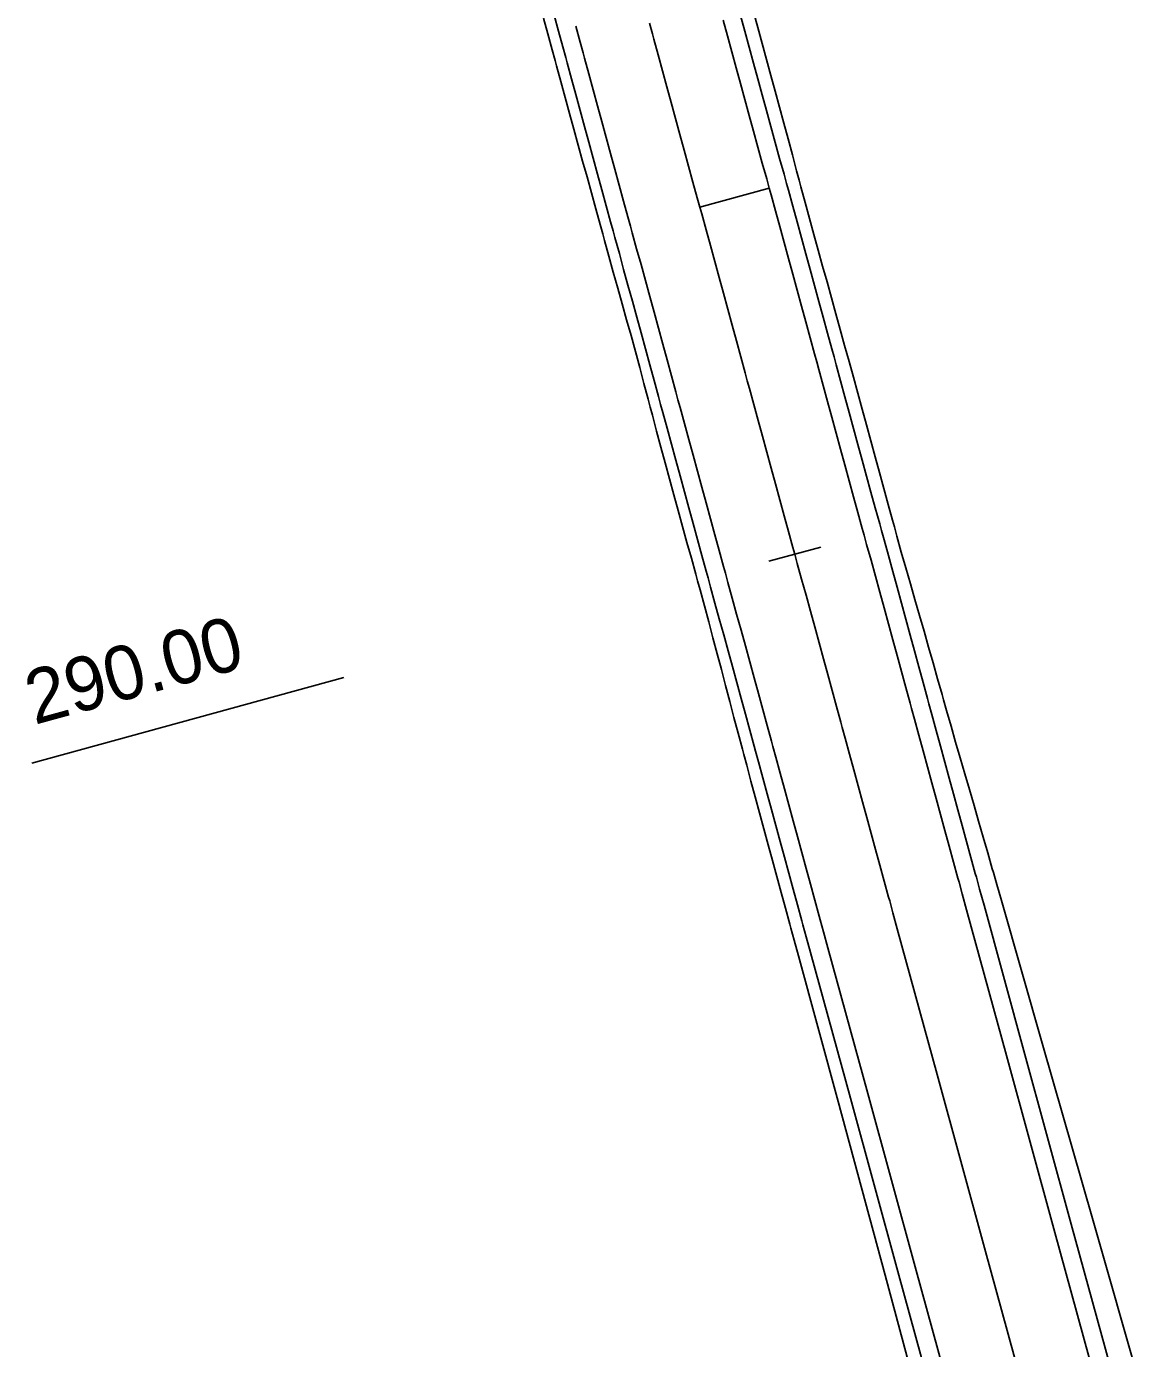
# Model space of a CAD drawing. Extents: x -550605 to -538780, y -1102367 to -1093705.
# Drawn here: x -547399.79 to -547368.77, y -1100986.96 to -1100950.2 of the extents above; entities that cross this region are included whole.
import ezdxf

# ---------------------------------------------------------------- set-up
doc = ezdxf.new("R2010")
doc.units = 0
for name, color, linetype in [('SIT - hrany vozovky', 7, 'Continuous'), ('SIT - osa cesty', 7, 'Continuous'), ('SIT - paty násypů', 7, 'Continuous'), ('SIT - staničení po 100m', 7, 'Continuous'), ('SIT - staničení po 30m', 7, 'Continuous')]:
    doc.layers.add(name, color=color, linetype=linetype)

msp = doc.modelspace()

# ---------------------------------------------------------------- linework, layer by layer
at = {"layer": 'SIT - hrany vozovky'}
for points in [[(-547374.237, -1100989.621), (-547375.55, -1100984.825), (-547376.87, -1100980.003), (-547377.978, -1100975.954), (-547378.099, -1100975.512), (-547378.19, -1100975.18), (-547378.22, -1100975.071), (-547378.341, -1100974.629), (-547378.462, -1100974.187), (-547378.583, -1100973.745), (-547378.703, -1100973.303), (-547378.824, -1100972.862), (-547378.945, -1100972.42), (-547379.066, -1100971.978), (-547379.187, -1100971.536), (-547379.308, -1100971.095), (-547379.429, -1100970.653), (-547379.51, -1100970.357), (-547379.55, -1100970.211), (-547379.671, -1100969.769), (-547379.792, -1100969.327), (-547379.913, -1100968.886), (-547380.034, -1100968.444), (-547380.155, -1100968.002), (-547380.275, -1100967.56), (-547380.396, -1100967.118), (-547380.517, -1100966.677), (-547380.638, -1100966.235), (-547380.759, -1100965.793), (-547380.83, -1100965.535), (-547380.88, -1100965.351), (-547381.001, -1100964.909), (-547381.122, -1100964.468), (-547381.243, -1100964.026), (-547381.364, -1100963.584), (-547381.485, -1100963.142), (-547381.606, -1100962.7), (-547381.726, -1100962.259), (-547381.847, -1100961.817), (-547381.968, -1100961.375), (-547382.089, -1100960.933), (-547382.15, -1100960.712), (-547382.21, -1100960.491), (-547382.331, -1100960.05), (-547382.452, -1100959.608), (-547382.573, -1100959.166), (-547382.694, -1100958.724), (-547382.815, -1100958.282), (-547382.936, -1100957.841), (-547383.057, -1100957.399), (-547383.178, -1100956.957), (-547383.298, -1100956.515), (-547383.419, -1100956.073), (-547383.47, -1100955.89), (-547383.54, -1100955.632), (-547383.661, -1100955.19), (-547383.782, -1100954.748), (-547383.903, -1100954.306), (-547384.024, -1100953.864), (-547384.145, -1100953.423), (-547384.266, -1100952.981), (-547384.387, -1100952.539), (-547384.508, -1100952.097), (-547384.629, -1100951.655), (-547384.75, -1100951.214), (-547384.79, -1100951.067), (-547384.87, -1100950.772), (-547384.991, -1100950.33), (-547385.112, -1100949.888)], [(-547369.897, -1100988.434), (-547371.21, -1100983.637), (-547372.53, -1100978.815), (-547373.638, -1100974.766), (-547373.759, -1100974.325), (-547373.849, -1100973.992), (-547373.879, -1100973.883), (-547374, -1100973.441), (-547374.121, -1100972.999), (-547374.242, -1100972.557), (-547374.363, -1100972.116), (-547374.484, -1100971.674), (-547374.605, -1100971.232), (-547374.726, -1100970.79), (-547374.847, -1100970.348), (-547374.968, -1100969.907), (-547375.089, -1100969.465), (-547375.169, -1100969.17), (-547375.21, -1100969.023), (-547375.33, -1100968.581), (-547375.451, -1100968.139), (-547375.572, -1100967.698), (-547375.693, -1100967.256), (-547375.814, -1100966.814), (-547375.935, -1100966.372), (-547376.056, -1100965.93), (-547376.177, -1100965.489), (-547376.298, -1100965.047), (-547376.419, -1100964.605), (-547376.489, -1100964.347), (-547376.54, -1100964.163), (-547376.661, -1100963.721), (-547376.782, -1100963.28), (-547376.902, -1100962.838), (-547377.023, -1100962.396), (-547377.144, -1100961.954), (-547377.265, -1100961.512), (-547377.386, -1100961.071), (-547377.507, -1100960.629), (-547377.628, -1100960.187), (-547377.749, -1100959.745), (-547377.809, -1100959.524), (-547377.87, -1100959.303), (-547377.991, -1100958.862), (-547378.112, -1100958.42), (-547378.233, -1100957.978), (-547378.353, -1100957.536), (-547378.474, -1100957.094), (-547378.595, -1100956.653), (-547378.716, -1100956.211), (-547378.837, -1100955.769), (-547378.958, -1100955.327), (-547379.079, -1100954.885), (-547379.129, -1100954.702), (-547379.2, -1100954.444), (-547379.321, -1100954.002), (-547379.442, -1100953.56), (-547379.563, -1100953.118), (-547379.684, -1100952.676), (-547379.805, -1100952.235), (-547379.925, -1100951.793), (-547380.046, -1100951.351), (-547380.167, -1100950.909), (-547380.288, -1100950.467), (-547380.409, -1100950.026)], [(-547369.415, -1100988.302), (-547370.727, -1100983.505), (-547372.047, -1100978.683), (-547373.155, -1100974.634), (-547373.276, -1100974.193), (-547373.367, -1100973.86), (-547373.397, -1100973.751), (-547373.518, -1100973.309), (-547373.639, -1100972.867), (-547373.76, -1100972.425), (-547373.881, -1100971.984), (-547374.002, -1100971.542), (-547374.123, -1100971.1), (-547374.244, -1100970.658), (-547374.365, -1100970.216), (-547374.485, -1100969.775), (-547374.606, -1100969.333), (-547374.687, -1100969.038), (-547374.727, -1100968.891), (-547374.848, -1100968.449), (-547374.969, -1100968.007), (-547375.09, -1100967.566), (-547375.211, -1100967.124), (-547375.332, -1100966.682), (-547375.453, -1100966.24), (-547375.574, -1100965.798), (-547375.695, -1100965.357), (-547375.816, -1100964.915), (-547375.936, -1100964.473), (-547376.007, -1100964.215), (-547376.057, -1100964.031), (-547376.178, -1100963.589), (-547376.299, -1100963.148), (-547376.42, -1100962.706), (-547376.541, -1100962.264), (-547376.662, -1100961.822), (-547376.783, -1100961.38), (-547376.904, -1100960.939), (-547377.025, -1100960.497), (-547377.146, -1100960.055), (-547377.267, -1100959.613), (-547377.327, -1100959.392), (-547377.388, -1100959.171), (-547377.508, -1100958.73), (-547377.629, -1100958.288), (-547377.75, -1100957.846), (-547377.871, -1100957.404), (-547377.992, -1100956.962), (-547378.113, -1100956.521), (-547378.234, -1100956.079), (-547378.355, -1100955.637), (-547378.476, -1100955.195), (-547378.597, -1100954.753), (-547378.647, -1100954.57), (-547378.718, -1100954.312), (-547378.839, -1100953.87), (-547378.96, -1100953.428), (-547379.08, -1100952.986), (-547379.201, -1100952.544), (-547379.322, -1100952.103), (-547379.443, -1100951.661), (-547379.564, -1100951.219), (-547379.685, -1100950.777), (-547379.806, -1100950.335), (-547379.927, -1100949.894)], [(-547373.755, -1100989.489), (-547375.068, -1100984.693), (-547376.388, -1100979.871), (-547377.496, -1100975.822), (-547377.617, -1100975.381), (-547377.708, -1100975.048), (-547377.738, -1100974.939), (-547377.858, -1100974.497), (-547377.979, -1100974.055), (-547378.1, -1100973.613), (-547378.221, -1100973.172), (-547378.342, -1100972.73), (-547378.463, -1100972.288), (-547378.584, -1100971.846), (-547378.705, -1100971.404), (-547378.826, -1100970.963), (-547378.947, -1100970.521), (-547379.028, -1100970.225), (-547379.068, -1100970.079), (-547379.189, -1100969.637), (-547379.309, -1100969.195), (-547379.43, -1100968.754), (-547379.551, -1100968.312), (-547379.672, -1100967.87), (-547379.793, -1100967.428), (-547379.914, -1100966.986), (-547380.035, -1100966.545), (-547380.156, -1100966.103), (-547380.277, -1100965.661), (-547380.347, -1100965.403), (-547380.398, -1100965.219), (-547380.519, -1100964.777), (-547380.64, -1100964.336), (-547380.761, -1100963.894), (-547380.881, -1100963.452), (-547381.002, -1100963.01), (-547381.123, -1100962.568), (-547381.244, -1100962.127), (-547381.365, -1100961.685), (-547381.486, -1100961.243), (-547381.607, -1100960.801), (-547381.667, -1100960.58), (-547381.728, -1100960.359), (-547381.849, -1100959.918), (-547381.97, -1100959.476), (-547382.091, -1100959.034), (-547382.212, -1100958.592), (-547382.333, -1100958.15), (-547382.453, -1100957.709), (-547382.574, -1100957.267), (-547382.695, -1100956.825), (-547382.816, -1100956.383), (-547382.937, -1100955.941), (-547382.987, -1100955.758), (-547383.058, -1100955.5), (-547383.179, -1100955.058), (-547383.3, -1100954.616), (-547383.421, -1100954.174), (-547383.542, -1100953.732), (-547383.663, -1100953.291), (-547383.784, -1100952.849), (-547383.904, -1100952.407), (-547384.025, -1100951.965), (-547384.146, -1100951.523), (-547384.267, -1100951.082), (-547384.307, -1100950.935), (-547384.388, -1100950.64), (-547384.509, -1100950.198)]]:
    msp.add_lwpolyline(points, dxfattribs=at)
at = {"layer": 'SIT - osa cesty'}
msp.add_lwpolyline([(-547371.826, -1100988.961), (-547373.139, -1100984.165), (-547374.459, -1100979.343), (-547375.567, -1100975.294), (-547375.688, -1100974.853), (-547375.779, -1100974.52), (-547375.808, -1100974.411), (-547375.929, -1100973.969), (-547376.05, -1100973.527), (-547376.171, -1100973.085), (-547376.292, -1100972.644), (-547376.413, -1100972.202), (-547376.534, -1100971.76), (-547376.655, -1100971.318), (-547376.776, -1100970.876), (-547376.897, -1100970.435), (-547377.018, -1100969.993), (-547377.098, -1100969.697), (-547377.139, -1100969.551), (-547377.26, -1100969.109), (-547377.38, -1100968.667), (-547377.501, -1100968.226), (-547377.622, -1100967.784), (-547377.743, -1100967.342), (-547377.864, -1100966.9), (-547377.985, -1100966.458), (-547378.106, -1100966.017), (-547378.227, -1100965.575), (-547378.348, -1100965.133), (-547378.418, -1100964.875), (-547378.469, -1100964.691), (-547378.59, -1100964.249), (-547378.711, -1100963.808), (-547378.831, -1100963.366), (-547378.952, -1100962.924), (-547379.073, -1100962.482), (-547379.194, -1100962.04), (-547379.315, -1100961.599), (-547379.436, -1100961.157), (-547379.557, -1100960.715), (-547379.678, -1100960.273), (-547379.738, -1100960.052), (-547379.799, -1100959.831), (-547379.92, -1100959.39), (-547380.041, -1100958.948), (-547380.162, -1100958.506), (-547380.283, -1100958.064), (-547380.403, -1100957.622), (-547380.524, -1100957.181), (-547380.645, -1100956.739), (-547380.766, -1100956.297), (-547380.887, -1100955.855), (-547381.008, -1100955.413), (-547381.058, -1100955.23), (-547381.129, -1100954.972), (-547381.25, -1100954.53), (-547381.371, -1100954.088), (-547381.492, -1100953.646), (-547381.613, -1100953.204), (-547381.734, -1100952.763), (-547381.855, -1100952.321), (-547381.975, -1100951.879), (-547382.096, -1100951.437), (-547382.217, -1100950.995), (-547382.338, -1100950.554), (-547382.378, -1100950.407), (-547382.459, -1100950.112)], dxfattribs=at)
at = {"layer": 'SIT - paty násypů'}
for points in [[(-547374.614, -1100989.725), (-547375.902, -1100984.922), (-547377.21, -1100980.096), (-547378.319, -1100976.048), (-547378.439, -1100975.606), (-547378.53, -1100975.273), (-547378.56, -1100975.164), (-547378.68, -1100974.722), (-547378.801, -1100974.28), (-547378.921, -1100973.838), (-547379.04, -1100973.396), (-547379.16, -1100972.954), (-547379.279, -1100972.511), (-547379.399, -1100972.069), (-547379.517, -1100971.627), (-547379.636, -1100971.184), (-547379.755, -1100970.742), (-547379.834, -1100970.446), (-547379.873, -1100970.299), (-547379.991, -1100969.857), (-547380.109, -1100969.414), (-547380.226, -1100968.971), (-547380.344, -1100968.529), (-547380.461, -1100968.086), (-547380.578, -1100967.643), (-547380.695, -1100967.2), (-547380.811, -1100966.757), (-547380.928, -1100966.314), (-547381.05, -1100965.872), (-547381.121, -1100965.615), (-547381.172, -1100965.431), (-547381.295, -1100964.99), (-547381.417, -1100964.548), (-547381.539, -1100964.107), (-547381.66, -1100963.665), (-547381.782, -1100963.223), (-547381.903, -1100962.782), (-547382.024, -1100962.34), (-547382.144, -1100961.898), (-547382.261, -1100961.455), (-547382.378, -1100961.012), (-547382.437, -1100960.791), (-547382.495, -1100960.569), (-547382.612, -1100960.126), (-547382.728, -1100959.683), (-547382.849, -1100959.241), (-547382.972, -1100958.8), (-547383.096, -1100958.359), (-547383.219, -1100957.918), (-547383.342, -1100957.477), (-547383.465, -1100957.036), (-547383.587, -1100956.594), (-547383.71, -1100956.153), (-547383.76, -1100955.969), (-547383.832, -1100955.711), (-547383.954, -1100955.27), (-547384.075, -1100954.828), (-547384.197, -1100954.387), (-547384.318, -1100953.945), (-547384.439, -1100953.503), (-547384.56, -1100953.061), (-547384.681, -1100952.619), (-547384.801, -1100952.177), (-547384.921, -1100951.736), (-547385.042, -1100951.293), (-547385.082, -1100951.147), (-547385.163, -1100950.852), (-547385.284, -1100950.41), (-547385.404, -1100949.968)], [(-547368.773, -1100988.126), (-547370.141, -1100983.345), (-547371.518, -1100978.538), (-547372.673, -1100974.502), (-547372.799, -1100974.062), (-547372.894, -1100973.731), (-547372.925, -1100973.622), (-547373.052, -1100973.181), (-547373.179, -1100972.741), (-547373.306, -1100972.301), (-547373.433, -1100971.861), (-547373.561, -1100971.421), (-547373.688, -1100970.981), (-547373.816, -1100970.541), (-547373.944, -1100970.101), (-547374.069, -1100969.661), (-547374.195, -1100969.22), (-547374.279, -1100968.926), (-547374.32, -1100968.78), (-547374.446, -1100968.339), (-547374.572, -1100967.899), (-547374.698, -1100967.458), (-547374.824, -1100967.018), (-547374.951, -1100966.578), (-547375.078, -1100966.137), (-547375.204, -1100965.697), (-547375.332, -1100965.257), (-547375.459, -1100964.817), (-547375.579, -1100964.375), (-547375.649, -1100964.117), (-547375.699, -1100963.933), (-547375.819, -1100963.491), (-547375.939, -1100963.049), (-547376.06, -1100962.607), (-547376.18, -1100962.165), (-547376.301, -1100961.723), (-547376.422, -1100961.282), (-547376.544, -1100960.84), (-547376.665, -1100960.398), (-547376.787, -1100959.957), (-547376.909, -1100959.515), (-547376.97, -1100959.294), (-547377.031, -1100959.074), (-547377.153, -1100958.632), (-547377.275, -1100958.191), (-547377.398, -1100957.75), (-547377.521, -1100957.308), (-547377.644, -1100956.867), (-547377.767, -1100956.426), (-547377.891, -1100955.985), (-547378.012, -1100955.543), (-547378.13, -1100955.1), (-547378.248, -1100954.658), (-547378.297, -1100954.474), (-547378.366, -1100954.215), (-547378.485, -1100953.773), (-547378.604, -1100953.331), (-547378.723, -1100952.888), (-547378.842, -1100952.446), (-547378.962, -1100952.004), (-547379.081, -1100951.562), (-547379.201, -1100951.12), (-547379.321, -1100950.678), (-547379.442, -1100950.236), (-547379.562, -1100949.794)]]:
    msp.add_lwpolyline(points, dxfattribs=at)
at = {"layer": 'SIT - staničení po 100m'}
msp.add_lwpolyline([(-547381.058, -1100955.23), (-547379.129, -1100954.702)], dxfattribs=at)
at = {"layer": 'SIT - staničení po 30m'}
for points in [[(-547379.142, -1100965.073), (-547377.695, -1100964.677)], [(-547399.638, -1100970.683), (-547390.957, -1100968.307)]]:
    msp.add_lwpolyline(points, dxfattribs=at)

# ---------------------------------------------------------------- texts
msp.add_text('290.00', height=1.5, rotation=15.307, dxfattribs=at).set_placement((-547399.567, -1100969.626))

doc.saveas('drawing.dxf')
